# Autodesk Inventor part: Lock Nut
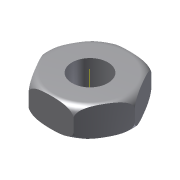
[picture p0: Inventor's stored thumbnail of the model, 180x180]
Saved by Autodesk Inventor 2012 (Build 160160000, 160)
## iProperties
Created: 2009-04
Part Number: Lock Nut
Document SubType Name: Modeling
Designer: Sham
Density: 1 g/cm^3
Material: Default
Author: Sham
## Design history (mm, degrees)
sketch "Sketch1"
  geometry: L1 (7.5, 12.99)-(15, 0); L2 (15, 0)-(7.5, -12.99); L3 (7.5, -12.99)-(-7.5, -12.99); L4 (-7.5, -12.99)-(-15, 0); L5 (-15, 0)-(-7.5, 12.99); L6 (-7.5, 12.99)-(7.5, 12.99); C1 r 6 at (0, 0); 1 further point
  constraints: 12 end point, 1 centre point, 1 coincident, 13 other
  dimensions: "d0" = 30 distance of L1.end L4.end; "d1" = 12 diameter of C1
extrude "Extrusion1" new body sketch "Sketch1" distance "d2" = 10; taper "d3" = 0 deg
sketch "Sketch2"
  geometry: L1 (-12, 0)-(-12, -0.022); L2 (-15, 7)-(-15, 3); L3 (0, -2.87)-(0, 12.87) reference; A1 r 3 centre (-12, 7) between (-12, 10) and (-15, 7); A2 r 3 centre (-12, 3) between (-15, 3) and (-12, 0)
  constraints: 4 end point, 4 point on circle, 2 centre point, 1 tangent
revolve "Revolution1" sketch "Sketch2" stored, may be unused: angle "d7" = 90 deg
body "Solid1"
other parameters: "d6" = 90 deg
